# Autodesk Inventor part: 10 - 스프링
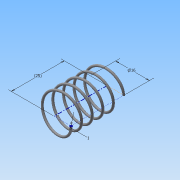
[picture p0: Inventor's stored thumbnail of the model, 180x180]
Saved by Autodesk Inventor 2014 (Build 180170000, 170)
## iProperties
Created: 2015-06
Part Number: 10 - 스프링
Material: 강철, 연강
Document SubType Name: Modeling
Designer: Administrator
Density: 1 g/cm^3
Appearance: 강철
Author: Administrator
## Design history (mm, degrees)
sketch "스케치1"
  geometry: L1 (0, 0)-(8, 0); L2 (8, 0)-(8, 21.5); L3 (8, 21.5)-(0, 21.5); L4 (0, 21.5)-(0, 0); C1 r 0.5 at (8, 0)
  constraints: 8 end point, 2 parallel, 1 centre point, 1 coincident, 1 horizontal, 1 perpendicular
  dimensions: "d0" = 21.5 distance between parallel lines of L1 L3 (derived); "d1" = 16 diameter of L2 L4; "d2" = 1 diameter of C1
feature "코일1" sketch "스케치1" pitch "d3" = 10; turns "d5" = 5; dims "d4" = 21.5 (= d0), "d6" = 0, angle "d7" = 90 deg, angle "d8" = 90 deg, "d9" = 0, "d10" = 0
node "작업 평면1"
sketch "스케치2"
  geometry: L1 (-8.5, 0)-(-7.5, 0) reference; 1 further point
  constraints: 1 horizontal alignment
extrude "돌출1" cut sketch "스케치2" distance "d12" = 10; taper "d13" = 0 deg
node "작업 평면2"
sketch "스케치3"
  geometry: L1 (-7.5, 0)-(-8.5, 0) reference; 1 further point
  constraints: 1 horizontal alignment
extrude "돌출2" cut sketch "스케치3" stored distance "d15" = 10; taper "d16" = 0 deg
node "솔리드1"
node "절단 모서리 투영1"
node "절단 모서리 투영2"
other parameters: "d11" = 0, "d14" = 21.5 (= d0)
